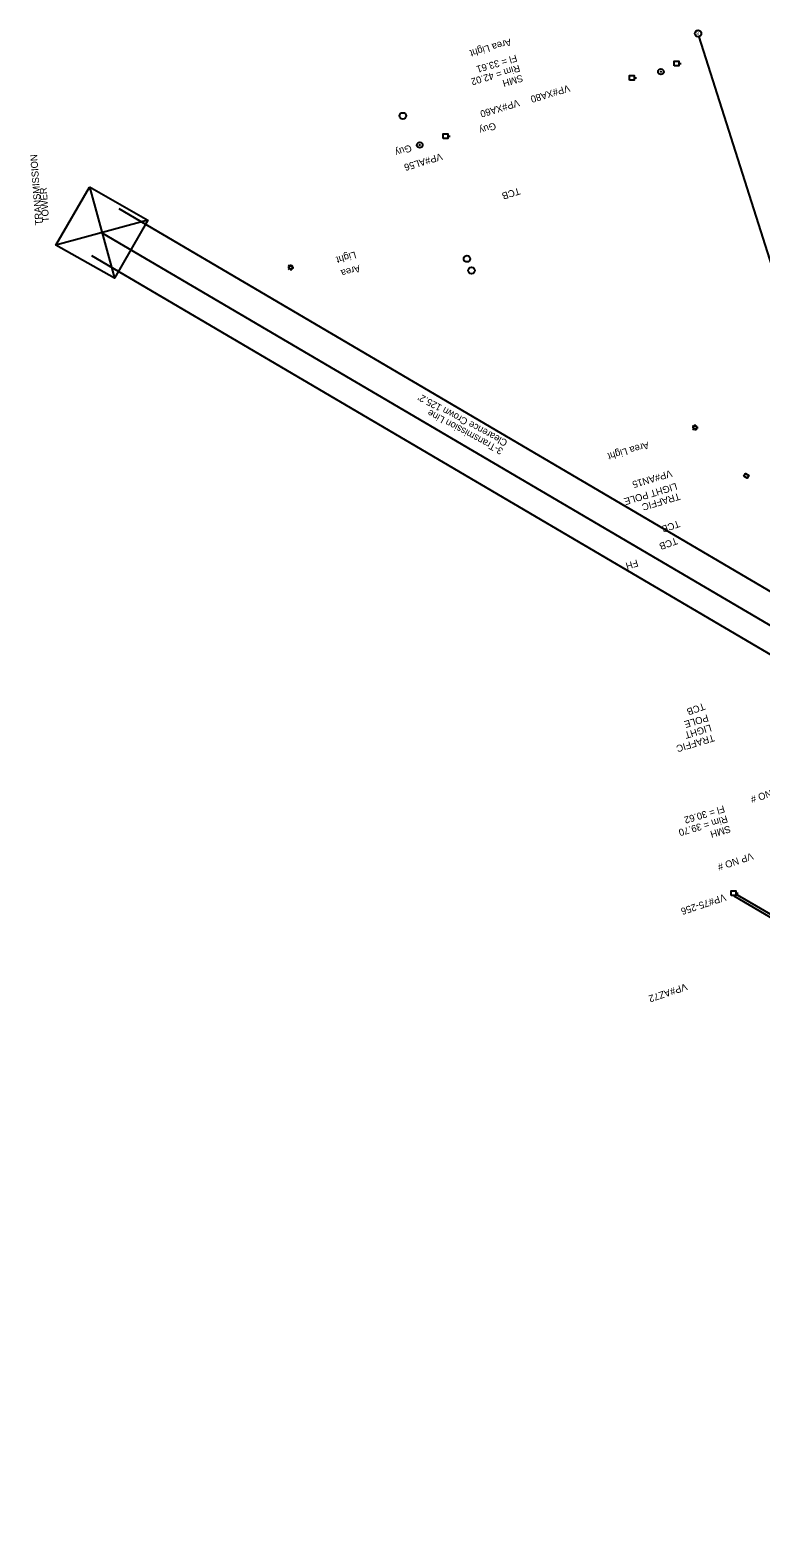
# Model space of a CAD drawing. Extents: x 3872070 to 3879223, y 293944 to 310567.
# Drawn here: x 3875693 to 3876007, y 301646 to 302295 of the extents above; entities that cross this region are included whole.
import ezdxf

# ---------------------------------------------------------------- set-up
doc = ezdxf.new("R2010")
doc.units = 0
for name, color, linetype in [('Level 11', 7, 'Continuous'), ('Level 3', 7, 'Continuous'), ('Level 33', 7, 'Continuous'), ('Level 34', 7, 'Continuous'), ('Level 35', 7, 'Continuous'), ('Level 39', 7, 'Continuous'), ('Level 4', 7, 'Continuous'), ('Level 7', 7, 'Continuous')]:
    doc.layers.add(name, color=color, linetype=linetype)

msp = doc.modelspace()

# ---------------------------------------------------------------- linework, layer by layer
at = {"layer": 'Level 11'}
for centre in [(3875852.86, 302258.11), (3875880.43, 302196.69), (3875882.33, 302191.61)]:
    msp.add_circle(centre, 1.41, dxfattribs=at)
at = {"layer": 'Level 3'}
msp.add_line((3876080.68, 301975.37), (3875980.32, 302292.19), dxfattribs=at)
msp.add_circle((3875979.81, 302293.63), 1.41, dxfattribs=at)
at = {"layer": 'Level 4'}
for p, q in [((3875971.58, 302280.69), (3875972.58, 302280.69)), ((3875952.31, 302274.57), (3875953.31, 302274.57)), ((3875872.26, 302249.36), (3875873.26, 302249.36)), ((3875718.1, 302227.65), (3875728.84, 302188.25)), ((3876332.58, 301864.21), (3875730.81, 302218.1)), ((3875743.21, 302213.3), (3875703.65, 302202.55)), ((3876325.63, 301853.67), (3875723.85, 302207.56)), ((3876320.83, 301844.07), (3875719.05, 302197.96)), ((3875803.91, 302192.93), (3875803.34, 302192.93)), ((3875804.12, 302193.44), (3875803.72, 302193.85)), ((3875803.72, 302192.01), (3875804.12, 302192.42)), ((3875804.64, 302193.66), (3875804.64, 302194.23)), ((3875804.64, 302192.21), (3875804.64, 302191.63)), ((3875805.15, 302193.44), (3875805.56, 302193.85)), ((3875805.56, 302192.01), (3875805.15, 302192.42)), ((3875805.36, 302192.93), (3875805.94, 302192.93)), ((3875977.79, 302124), (3875977.21, 302124)), ((3875978, 302124.51), (3875977.59, 302124.92)), ((3875977.59, 302123.08), (3875978, 302123.49)), ((3875978.51, 302124.73), (3875978.51, 302125.3)), ((3875978.51, 302123.28), (3875978.51, 302122.7)), ((3875979.02, 302124.51), (3875979.43, 302124.92)), ((3875979.43, 302123.08), (3875979.02, 302123.49)), ((3875979.24, 302124), (3875979.81, 302124)), ((3875995.22, 301922.48), (3876467.43, 301646.27)), ((3875995.94, 301923.44), (3876468.15, 301647.23)), ((3875996.11, 301923.62), (3875997.11, 301923.62))]:
    msp.add_line(p, q, dxfattribs=at)
for points in [[(3875969.58, 302279.69), (3875969.58, 302281.69), (3875971.58, 302281.69), (3875971.58, 302279.69)], [(3875950.31, 302273.57), (3875950.31, 302275.57), (3875952.31, 302275.57), (3875952.31, 302273.57)], [(3875870.26, 302248.36), (3875870.26, 302250.36), (3875872.26, 302250.36), (3875872.26, 302248.36)], [(3875994.11, 301922.62), (3875994.11, 301924.62), (3875996.11, 301924.62), (3875996.11, 301922.62)]]:
    msp.add_lwpolyline(points, close=True, dxfattribs=at)
msp.add_lwpolyline([(3875718.1, 302227.65), (3875743.21, 302213.3), (3875728.84, 302188.25), (3875703.65, 302202.55), (3875718.12, 302227.53)], dxfattribs=at)
for centre, radius in [((3875963.85, 302277.16), 1.22), ((3875963.85, 302277.16), 0.0992), ((3875963.85, 302277.16), 0.0483), ((3875860.13, 302245.6), 1.22), ((3875860.13, 302245.6), 0.0992), ((3875860.13, 302245.6), 0.0483), ((3875804.64, 302192.93), 0.725), ((3875978.51, 302124), 0.725)]:
    msp.add_circle(centre, radius, dxfattribs=at)
at = {"layer": 'Level 7'}
msp.add_lwpolyline([(3875999.55, 302103.06), (3876000.19, 302104.23), (3876001.65, 302103.43), (3876001, 302102.26)], close=True, dxfattribs=at)

# ---------------------------------------------------------------- texts
at = {"layer": 'Level 3'}
msp.add_text('S', height=1.41, rotation=180, dxfattribs=at).set_placement((3875980.29, 302294.34))
at = {"layer": 'Level 33'}
for s, p in [('Fl = 33.61', (3875901.47, 302284.54)), ('Rim = 42.02', (3875902.74, 302280.22)), ('SMH', (3875904, 302275.91)), ('Fl = 30.62', (3875990.8, 301961.46)), ('Rim = 39.70', (3875992.06, 301957.15)), ('SMH', (3875993.33, 301952.83))]:
    msp.add_text(s, height=3, rotation=196.31202, dxfattribs=at).set_placement(p)
at = {"layer": 'Level 34'}
for s, rotation, p in [('Area Light', 196.27955, (3875898.97, 302291.45)), ('VP#XA80', 196.8469, (3875924.17, 302271.6)), ('VP#XA60', 196.8469, (3875902.47, 302265.28)), ('Guy', 198.99034, (3875892.31, 302255.4)), ('Guy', 198.99034, (3875856.04, 302245.85)), ('TRANSMISSION', 94.26422, (3875697.81, 302211.21)), ('VP#AL56', 196.8469, (3875869.33, 302242.18)), (' TOWER', 94.26422, (3875700.82, 302211.43)), ('Light', 196.27955, (3875832.27, 302199.86)), ('Area', 196.27955, (3875834.08, 302194.06)), ("Clearence Crown 125.2'", 151.73939, (3875898.15, 302118.35)), ('3-Transmission Line', 151.73939, (3875896.25, 302114.83)), ('Area Light', 196.27955, (3875958.21, 302117.99)), ('VP#AN15', 196.66042, (3875968.12, 302105.84)), ('VP NO #', 198.45225, (3876017.13, 301970.26)), ('VP NO #', 198.45225, (3876002.94, 301941.16)), ('VP#75-256', 198.45225, (3875991.18, 301923.44)), ('VP#AZ72', 198.45225, (3875974.57, 301884.93))]:
    msp.add_text(s, height=3, rotation=rotation, dxfattribs=at).set_placement(p)
at = {"layer": 'Level 35'}
msp.add_text('FH', height=3, rotation=196.99479, dxfattribs=at).set_placement((3875953.52, 302067.28))
at = {"layer": 'Level 39'}
for s, rotation, p in [('TCB', 197.72267, (3875902.78, 302227.36)), ('LIGHT POLE', 196.79134, (3875970.29, 302100.28)), ('TRAFFIC', 196.79134, (3875971.59, 302095.97)), ('TCB', 199.72381, (3875971.33, 302084.19)), ('TCB', 199.72381, (3875970.34, 302076.81)), ('TCB', 199.72381, (3875982.19, 302005.63)), ('POLE', 196.79134, (3875983.77, 302000.65)), ('TRAFFIC', 196.79134, (3875986.37, 301992.04)), ('LIGHT', 196.79134, (3875985.07, 301996.35))]:
    msp.add_text(s, height=3, rotation=rotation, dxfattribs=at).set_placement(p)

doc.saveas('drawing.dxf')
